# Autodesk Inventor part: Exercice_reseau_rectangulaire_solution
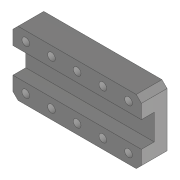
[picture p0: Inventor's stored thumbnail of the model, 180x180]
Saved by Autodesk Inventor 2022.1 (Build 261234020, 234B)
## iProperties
Created: 2014-06
Part Number: Exercice_reseau_rectangulaire_solution
Material: Générique
Document SubType Name: Modeling
Designer: Fabian
Density: 1 g/cm^3
Appearance: Gris clair
Mass: 9.21314 g
Surface Area: 51.3824 cm^2
Volume: 9.21314 cm^3
Author: Fabian
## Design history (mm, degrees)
sketch "Esquisse1"
  geometry: L1 (-23, 12.5)-(23, 12.5); L2 (25, 10.5)-(25, -10.5); L3 (23, -12.5)-(-23, -12.5); L4 (-25, -10.5)-(-25, 10.5); L5 (0, 12.5)-(0, -12.5); L6 (-25, 10.5)-(-23, 12.5); L7 (-25, -10.5)-(-23, -12.5); L8 (25, -10.5)-(23, -12.5); L9 (23, 12.5)-(25, 10.5); L10 (-25, 0)-(25, 0); L11 (-25, 5)-(25, 5); L12 (-25, -5)-(25, -5); 6 further points
  constraints: 24 end point, 12 point on line, 5 midpoint, 2 parallel, 2 perpendicular, 1 coincident, 1 horizontal
  dimensions: "d0" = 50 distance of point (-25, 12.5) point (25, 12.5); "d1" = 25 distance of point (-25, -12.5) point (-25, 12.5) (= 0.5 x d0); "d2" = 2 distance of L4.end point (-25, 12.5); "d3" = 2 distance of L1.start point (-25, 12.5) (= d2); "d4" = 2 distance of L4.start point (-25, -12.5) (= d2); "d5" = 2 distance of L3.end point (-25, -12.5) (= d4); "d6" = 2 distance of L2.end point (25, -12.5) (= d2); "d7" = 2 distance of L3.start point (25, -12.5) (= d6); "d8" = 2 distance of L1.end point (25, 12.5) (= d2); "d9" = 2 distance of L2.start point (25, 12.5) (= d8); "d14" = 10 distance between parallel lines of L12 L11; "d15" = 7.5 distance between parallel lines of L3 L12
extrude "Extrusion1" new body sketch "Esquisse1" distance "d16" = 5; taper "d17" = 0 deg
extrude "Extrusion2" join sketch "Esquisse1" distance "d18" = 5; taper "d19" = 0 deg
sketch "Esquisse2"
  geometry: L1 (23, 12.5)-(-23, 12.5) reference; L2 (25, 5)-(25, 10.5) reference; 2 further points
  dimensions: "d20" = 3.75 distance from line of L1 point (0, 8.75) (= 0.5 x d15); "d21" = 25 distance from line of L2 point (0, 8.75) (= 0.5 x d0)
hole "Perçage1" sketch "Esquisse2" at (0, 8.75) diameter "d22" = 3; stored, may be unused: countersink angle "d26" = 82 deg, drill point angle "d28" = 118 deg; dims "d23" = 6, "d24" = 3.023, "d25" = 2, "d27" = 8
pattern_linear "Réseau rectangulaire1" dims "d31" = 10, "d34" = 17.5 (= d1 - d15)
node "Solide1"
